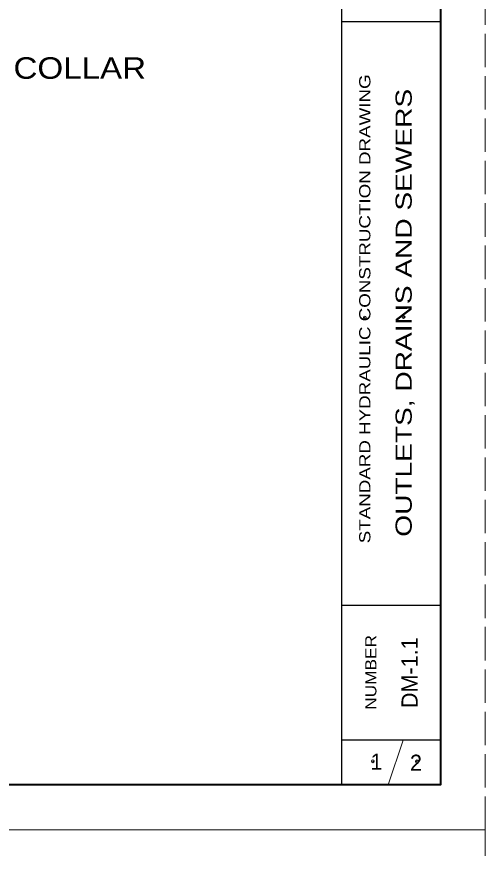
# Model space of a CAD drawing. Extents: x 1083.1 to 1117.1, y 697.4 to 741.4.
# Drawn here: x 1111.91 to 1117.13, y 719.1 to 728.41 of the extents above; entities that cross this region are included whole.
import ezdxf
from ezdxf.enums import TextEntityAlignment as Align

# ---------------------------------------------------------------- set-up
doc = ezdxf.new("R2010")
doc.units = 0
doc.header["$LTSCALE"] = 0.062
doc.header["$PDMODE"] = 32
doc.header["$PDSIZE"] = 0.031
doc.linetypes.add('LONG_DASHED', pattern=[7.5, 6, -1.5])
doc.layers.add('1', color=7, linetype='Continuous', lineweight=13)

msp = doc.modelspace()

# ---------------------------------------------------------------- linework, layer by layer
at = {"layer": '1', "lineweight": 25}
for p, q in [((1115.52642, 719.85408), (1115.52642, 740.85408)), ((1116.62642, 740.85408), (1116.62642, 719.85408)), ((1116.62642, 728.35408), (1115.52642, 728.35408)), ((1116.62642, 721.85408), (1115.52642, 721.85408)), ((1116.62642, 720.35408), (1115.52642, 720.35408))]:
    msp.add_line(p, q, dxfattribs=at)
at = {"layer": '1'}
msp.add_line((1116.04308, 719.85408), (1116.20975, 720.35408), dxfattribs=at)
at = {"layer": '1', "linetype": 'LONG_DASHED'}
for points in [[(1083.12642, 719.35408), (1117.12642, 719.35408), (1117.12642, 741.35408), (1083.12642, 741.35408)], [(1083.12642, 697.35408), (1117.12642, 697.35408), (1117.12642, 719.35408), (1083.12642, 719.35408)]]:
    msp.add_lwpolyline(points, close=True, dxfattribs=at)
at = {"layer": '1', "lineweight": 25}
msp.add_lwpolyline([(1116.62642, 719.85408), (1085.12642, 719.85408), (1085.12642, 740.85408)], dxfattribs=at)
at = {"layer": '1', "lineweight": 40}
msp.add_lwpolyline([(1085.12642, 740.85408), (1116.62642, 740.85408), (1116.62642, 719.85408), (1085.12642, 719.85408)], close=True, dxfattribs=at)
msp.add_lwpolyline([(1085.12642, 740.85408), (1116.62642, 740.85408), (1116.62642, 719.85408), (1085.12642, 719.85408)], close=True, dxfattribs=at)
at = {"layer": '1'}
for p in [(1115.78383, 725.06008), (1116.21667, 725.06742), (1115.8745, 720.11783), (1116.36292, 720.11683)]:
    msp.add_point(p, dxfattribs=at)

# ---------------------------------------------------------------- texts
at = {"layer": '1', "width": 1.15}
msp.add_text('MASONRY COLLAR', height=0.24, dxfattribs=at).set_placement((1109.90142, 727.72092))
at = {"layer": '1'}
for s, height, width, p in [('STANDARD HYDRAULIC CONSTRUCTION DRAWING', 0.125, 1.25, (1115.84633, 725.15812)), ('OUTLETS, DRAINS AND SEWERS', 0.18, 1.3, (1116.30683, 725.11421)), ('NUMBER', 0.125, 1.15, (1115.91342, 721.10817))]:
    msp.add_text(s, height=height, rotation=90, dxfattribs=dict(at, width=width)).set_placement(p, align=Align.CENTER)
msp.add_text('DM-1.1', height=0.18, rotation=90, dxfattribs=at).set_placement((1116.3725, 721.10442), align=Align.CENTER)
for s, p in [('1', (1115.91427, 720.02417)), ('2', (1116.35371, 720.01158))]:
    msp.add_text(s, height=0.18, dxfattribs=at).set_placement(p, align=Align.CENTER)

doc.saveas('drawing.dxf')
